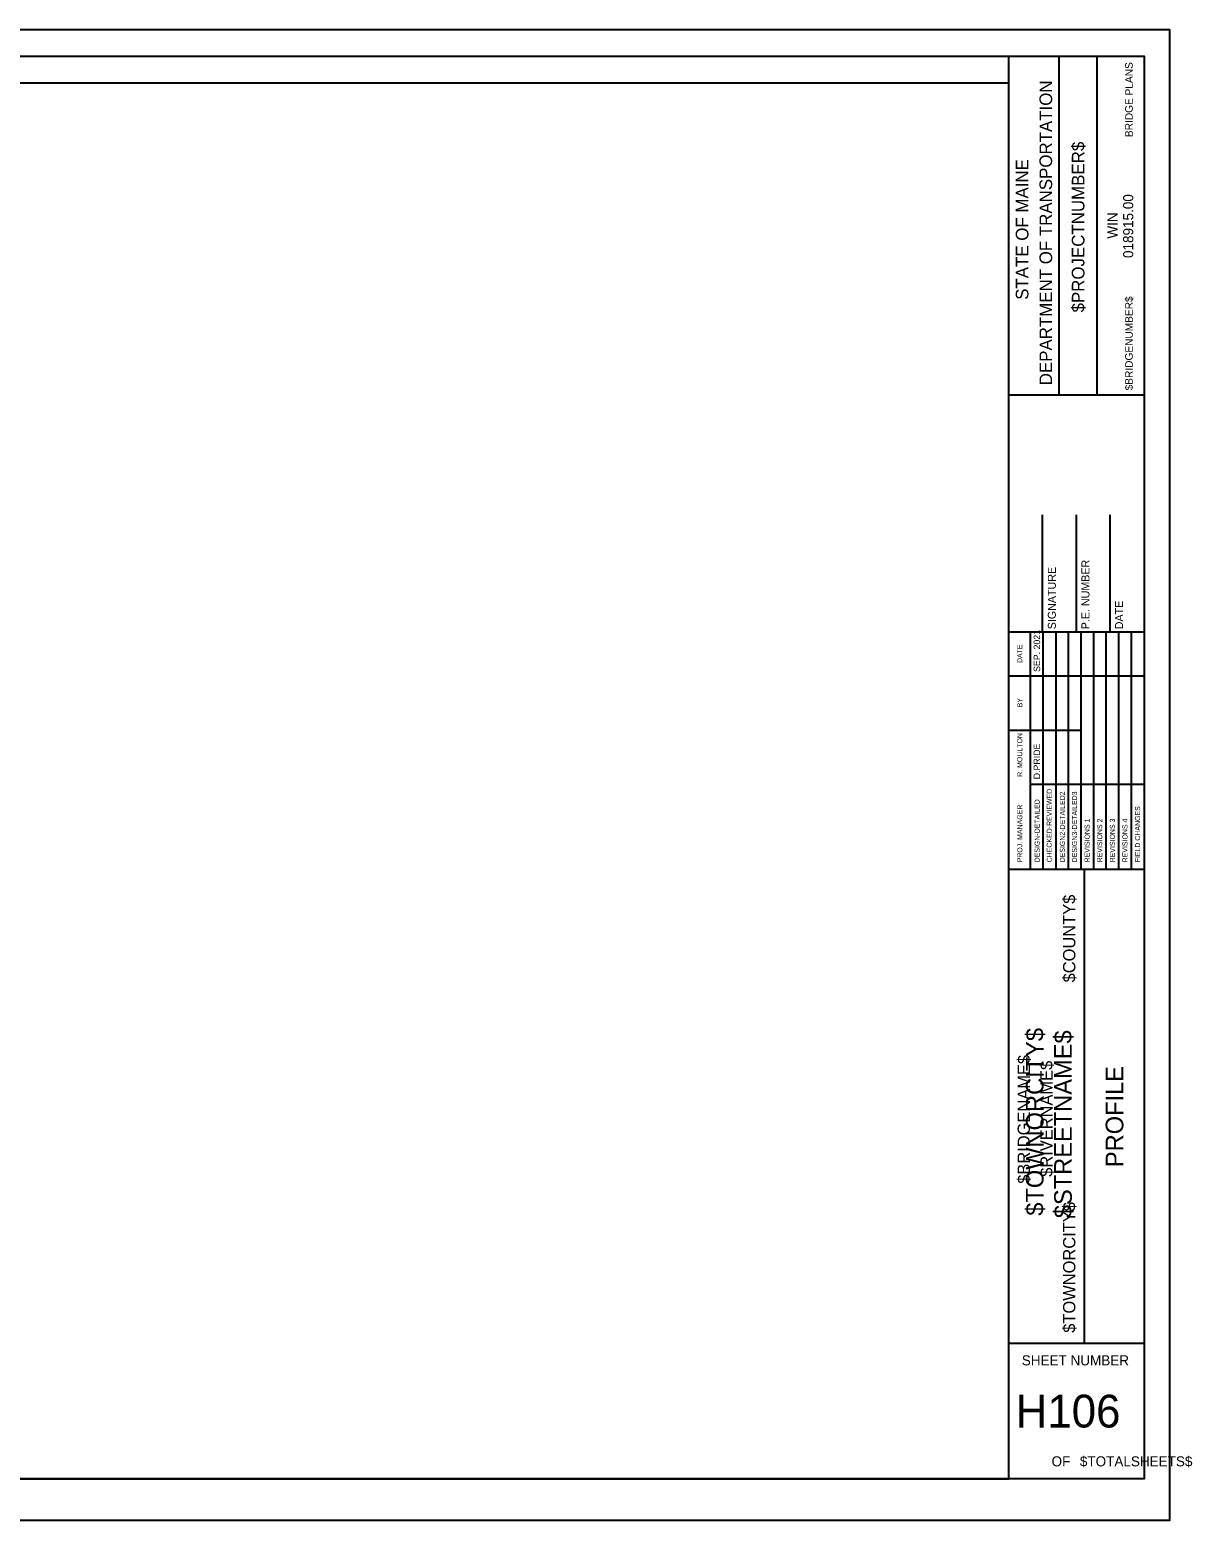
# Model space of a CAD drawing. Extents: x 37509 to 38367, y 9985 to 10535.
# Drawn here: x 37938 to 38367, y 9985 to 10535 of the extents above; entities that cross this region are included whole.
import ezdxf

# ---------------------------------------------------------------- set-up
doc = ezdxf.new("R2010")
doc.units = 0
for name, color, linetype in [('BORDER', 7, 'Continuous'), ('BRIDGE_TITLE', 7, 'Continuous'), ('CLIPS', 7, 'Continuous'), ('HIGHWAY_TITLE', 7, 'Continuous'), ('PLOT BOUNDARY', 7, 'Continuous')]:
    doc.layers.add(name, color=color, linetype=linetype)

msp = doc.modelspace()

# ---------------------------------------------------------------- linework, layer by layer
at = {"layer": 'BORDER'}
for p, q in [((38299.44, 10000), (38299.44, 10525)), ((38318.08, 10399.99), (38318.08, 10524.99)), ((38332.06, 10399.99), (38332.06, 10524.99)), ((38299.44, 10399.97), (38349.44, 10399.97)), ((38311.94, 10312.51), (38311.94, 10355.75)), ((38324.44, 10312.51), (38324.44, 10355.75)), ((38336.94, 10312.51), (38336.94, 10355.75)), ((38299.44, 10312.51), (38349.44, 10312.51)), ((38299.44, 10225.01), (38349.44, 10225.01)), ((38327.39, 10050.01), (38327.39, 10225.01)), ((38299.44, 10050.01), (38349.44, 10050.01))]:
    msp.add_line(p, q, dxfattribs=at)
msp.add_lwpolyline([(37549.44, 10525), (38349.44, 10525), (38349.44, 10000), (37549.44, 10000)], close=True, dxfattribs=at)
for points in [[(38307.51, 10296.26), (38307.51, 10312.51)], [(38312.18, 10225.03), (38312.18, 10312.51)], [(38316.83, 10312.51), (38316.83, 10225.03)], [(38321.49, 10225.03), (38321.49, 10312.51)], [(38326.15, 10225.03), (38326.15, 10312.51)], [(38330.81, 10225.03), (38330.81, 10312.51)], [(38335.47, 10225.03), (38335.47, 10312.51)], [(38340.13, 10225.03), (38340.13, 10312.51)], [(38344.79, 10225.03), (38344.79, 10312.51)], [(38307.52, 10225.03), (38307.52, 10308.98)], [(38299.44, 10296.26), (38349.44, 10296.26)], [(38299.44, 10276.26), (38307.52, 10276.26)], [(38307.51, 10276.26), (38326.15, 10276.26)], [(38307.51, 10256.26), (38349.44, 10256.26)]]:
    msp.add_lwpolyline(points, dxfattribs=at)
at = {"layer": 'CLIPS'}
msp.add_lwpolyline([(37549.44, 10000), (38299.44, 10000), (38299.44, 10515), (37549.44, 10515)], close=True, dxfattribs=at)
at = {"layer": 'PLOT BOUNDARY'}
msp.add_lwpolyline([(37508.97, 9984.7), (38358.97, 9984.7), (38358.97, 10534.7), (37508.97, 10534.7)], close=True, dxfattribs=at)

# ---------------------------------------------------------------- texts
at = {"layer": 'BORDER'}
for s, height, rotation, p in [('DEPARTMENT OF TRANSPORTATION', 4.6588, 90, (38315.47, 10403.53)), ('$PROJECTNUMBER$', 4.6588, 90, (38327.4, 10430.4)), ('STATE OF MAINE', 4.6588, 90, (38306.72, 10435.06)), ('018915.00', 3.726, 90, (38345.42, 10450.49)), ('WIN', 3.726, 90, (38339.62, 10457.65)), ('SIGNATURE', 2.953, 90, (38316.84, 10313.48)), ('P.E. NUMBER', 2.9528, 90, (38329.24, 10313.48)), ('DATE', 2.953, 90, (38341.64, 10313.48)), ('SEP. 2021', 2.423, 90, (38311.05, 10297.74)), ('DATE', 1.857, 90, (38304.46, 10301.04)), ('BY', 1.857, 90, (38304.46, 10284.69)), ('R. MOULTON', 1.864, 90, (38304.46, 10259.03)), ('D.PRIDE', 2.423, 90, (38311.05, 10258.13)), ('CHECKED-REVIEWED', 1.8637, 90, (38315.34, 10227.46)), ('DESIGN2-DETAILED2', 1.8637, 90, (38320.19, 10227.46)), ('DESIGN3-DETAILED3', 1.8637, 90, (38324.66, 10227.46)), ('PROJ. MANAGER', 1.8637, 90, (38304.46, 10227.46)), ('DESIGN-DETAILED', 1.8637, 90, (38310.87, 10227.46)), ('FIELD CHANGES', 1.8637, 90, (38347.95, 10227.46)), ('REVISIONS 1', 1.8637, 90, (38329.32, 10227.46)), ('REVISIONS 2', 1.8637, 90, (38333.98, 10227.46)), ('REVISIONS 3', 1.8637, 90, (38338.64, 10227.46)), ('REVISIONS 4', 1.8637, 90, (38343.29, 10227.46)), ('PROFILE', 6.521, 90, (38341.76, 10115)), ('SHEET NUMBER', 3.7264, 360, (38304.27, 10041.83)), ('H106', 12.097, 360, (38302.02, 10018.91)), ('OF', 3.726, 360, (38315.27, 10004.56)), ('$TOTALSHEETS$', 3.7264, 360, (38325.72, 10004.56))]:
    msp.add_text(s, height=height, rotation=rotation, dxfattribs=at).set_placement(p)
at = {"layer": 'BRIDGE_TITLE'}
for s, height, p in [('BRIDGE PLANS', 2.795, (38345.23, 10495.12)), ('$BRIDGENUMBER$', 2.795, (38345.23, 10401.65)), ('$COUNTY$', 4.536, (38324.04, 10183.17)), ('$BRIDGENAME$', 4.5358, (38307.27, 10108.86)), ('$RIVERNAME$', 4.5358, (38315.65, 10111.43)), ('$TOWNORCITY$', 4.5358, (38324.04, 10053.88))]:
    msp.add_text(s, height=height, rotation=90, dxfattribs=at).set_placement(p)
at = {"layer": 'HIGHWAY_TITLE'}
for s, p in [('$TOWNORCITY$', (38312.3, 10097.06)), ('$STREETNAME$', (38322.74, 10096.16))]:
    msp.add_text(s, height=6.5214, rotation=90, dxfattribs=at).set_placement(p)

doc.saveas('drawing.dxf')
